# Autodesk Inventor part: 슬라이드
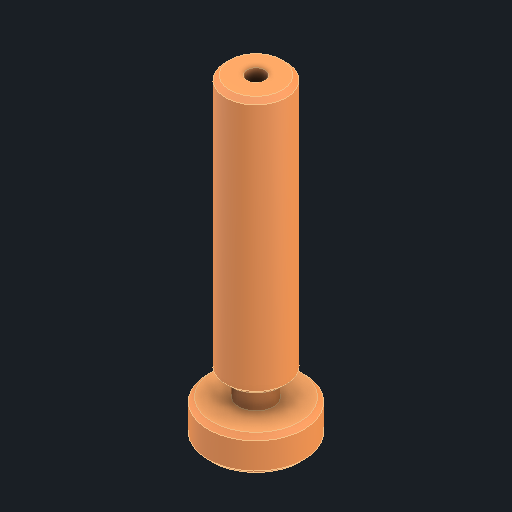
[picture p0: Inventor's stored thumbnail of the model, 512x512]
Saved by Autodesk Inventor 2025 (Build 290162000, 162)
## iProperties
Created: 2025-08
Part Number: 슬라이드
Material: 강철, 연강
Document SubType Name: Modeling
Designer: infra012
Density: 7.86 g/cm^3
Appearance: 기본값
Author: jhkim
Sending System: Autodesk Inventor 2026
Preprocessor: ST-DEVELOPER v20.1
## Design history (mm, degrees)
sketch "스케치1"
  geometry: 1 further point
  constraints: 1 other
feature "솔리드1"
node "솔리드2"
